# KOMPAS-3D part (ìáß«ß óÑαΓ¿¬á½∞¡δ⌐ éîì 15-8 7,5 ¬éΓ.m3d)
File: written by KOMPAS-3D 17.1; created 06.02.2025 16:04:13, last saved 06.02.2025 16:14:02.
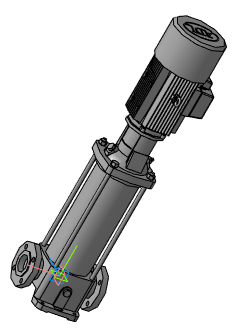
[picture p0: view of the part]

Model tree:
1. Операция без истории:1  (labels: Насос вертикальный ВМН 15-8 7,5 кВт)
